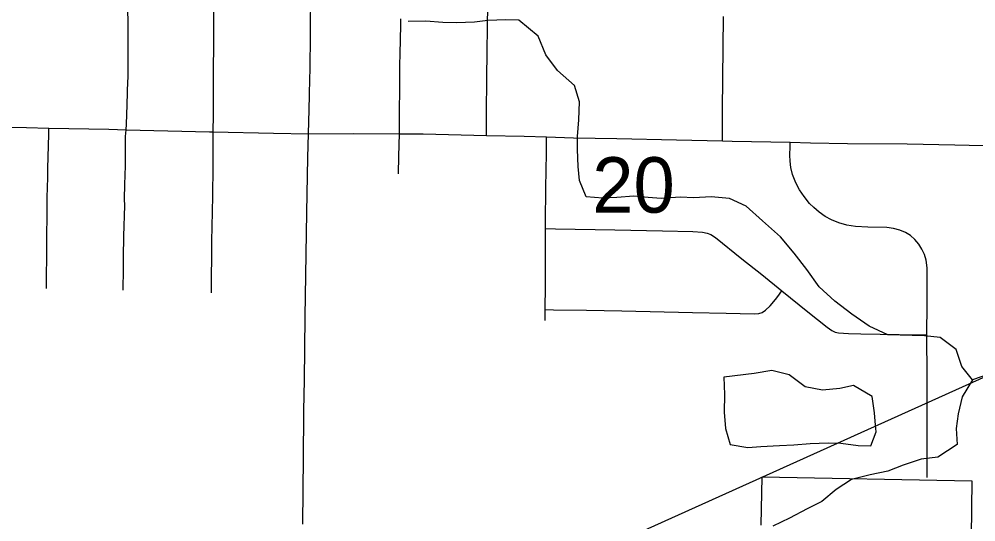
# Model space of a CAD drawing. Extents: x 0 to 34, y 0 to 22.
# Drawn here: x 6.731 to 7.454, y 16.761 to 17.141 of the extents above; entities that cross this region are included whole.
import ezdxf

# ---------------------------------------------------------------- set-up
doc = ezdxf.new("R2010")
doc.units = 0
for name, color, linetype in [('GM_X_City_Street', 7, 'Continuous'), ('GM_X_Corporation', 7, 'Continuous'), ('GM_X_County_Road', 7, 'Continuous'), ('GM_X_Minor_Lake', 7, 'Continuous'), ('GM_X_Minor_River', 7, 'Continuous'), ('GM_X_Section_Text', 7, 'Continuous'), ('GM_X_State_Route', 7, 'Continuous'), ('GM_X_US_Route', 7, 'Continuous'), ('SH_Data', 7, 'Continuous')]:
    doc.layers.add(name, color=color, linetype=linetype)

msp = doc.modelspace()

# ---------------------------------------------------------------- linework, layer by layer
at = {"layer": 'GM_X_City_Street'}
for points in [[(7.08428, 17.05289), (7.08428, 17.05616), (7.08427, 17.06975), (7.08456, 17.09583), (7.08478, 17.11632), (7.08501, 17.13421), (7.08585, 17.18692)], [(6.81005, 16.93612), (6.81018, 16.95227), (6.81013, 16.956), (6.81018, 16.95966), (6.81019, 16.96091), (6.81043, 16.97698), (6.81117, 16.99994), (6.81111, 17.00489), (6.81107, 17.00718), (6.81111, 17.01021), (6.81122, 17.01087), (6.81134, 17.01579), (6.81171, 17.02995), (6.81177, 17.05199), (6.81222, 17.05721), (6.81258, 17.06137), (6.81307, 17.07601), (6.81356, 17.09432), (6.81366, 17.09552), (6.81368, 17.10735), (6.81367, 17.13345), (6.81365, 17.13778), (6.81355, 17.1482)], [(6.87661, 16.93418), (6.87704, 16.97308), (6.87747, 16.99513), (6.87762, 17.0073), (6.87794, 17.02894), (6.87804, 17.05561), (6.87809, 17.06845), (6.87828, 17.10326), (6.87832, 17.12059), (6.87834, 17.13278), (6.87847, 17.14813)], [(7.01784, 17.02383), (7.0182, 17.03722), (7.01853, 17.05416), (7.01882, 17.10495), (7.01903, 17.11547), (7.01931, 17.12415), (7.0194, 17.1254), (7.01942, 17.12913), (7.01948, 17.1322), (7.01967, 17.14089)], [(6.75221, 16.93733), (6.75222, 16.94221), (6.75218, 16.94654), (6.75231, 16.96142), (6.75245, 16.98001), (6.75256, 16.98929), (6.75267, 16.99728), (6.75273, 17.00035), (6.7527, 17.00212), (6.75273, 17.0064), (6.75289, 17.01323), (6.75302, 17.02131), (6.75314, 17.028), (6.75378, 17.05392), (6.75389, 17.05848)], [(7.12851, 16.91329), (7.12857, 16.92148), (7.1287, 16.93927), (7.12877, 16.98263), (7.12878, 16.98721), (7.12911, 17.01336), (7.12953, 17.0395), (7.12952, 17.04838), (7.12952, 17.05175)], [(7.41688, 16.79467), (7.41689, 16.80583), (7.41682, 16.84054), (7.41688, 16.8536), (7.41693, 16.87097), (7.41676, 16.90239), (7.41674, 16.90576), (7.41691, 16.9225), (7.41702, 16.94363), (7.41688, 16.95301), (7.41612, 16.95867), (7.41487, 16.96297), (7.41299, 16.96705), (7.41054, 16.97083), (7.40762, 16.97425), (7.40428, 16.97724), (7.4005, 16.97969), (7.39637, 16.98146), (7.39143, 16.9827), (7.3864, 16.98332), (7.37208, 16.98363), (7.36287, 16.98418), (7.35623, 16.98524), (7.35035, 16.98684), (7.34467, 16.9891), (7.33986, 16.9917), (7.33539, 16.99485), (7.33127, 16.99851), (7.32822, 17.00148), (7.32398, 17.00668), (7.32056, 17.01176), (7.31778, 17.01719), (7.31536, 17.02346), (7.31402, 17.02874), (7.31345, 17.03357), (7.31337, 17.03791), (7.31352, 17.04458), (7.3136, 17.04768)], [(7.12877, 16.98263), (7.13632, 16.98249), (7.18103, 16.98166), (7.21706, 16.98089), (7.24003, 16.98044), (7.24735, 16.97992), (7.25083, 16.97916), (7.25354, 16.97803), (7.25707, 16.97573), (7.27693, 16.95986), (7.29201, 16.94785), (7.30728, 16.93559), (7.32689, 16.91984), (7.34137, 16.90812), (7.34508, 16.90556), (7.34748, 16.90447), (7.35004, 16.90385), (7.35758, 16.90336), (7.36695, 16.90327), (7.41041, 16.9025), (7.41676, 16.90239)], [(7.12857, 16.92148), (7.13489, 16.92137), (7.15971, 16.92092), (7.1864, 16.92046), (7.23977, 16.91916), (7.26523, 16.91876), (7.28629, 16.91818), (7.28982, 16.91847), (7.29248, 16.91938), (7.29491, 16.92097), (7.29842, 16.92429), (7.30238, 16.92896), (7.3042, 16.93144), (7.30728, 16.93559)]]:
    msp.add_lwpolyline(points, dxfattribs=at)
at = {"layer": 'GM_X_Corporation'}
msp.add_lwpolyline([(7.29168, 16.75869), (7.29237, 16.79534), (7.45064, 16.79234), (7.44905, 16.66612)], dxfattribs=at)
at = {"layer": 'GM_X_County_Road'}
for points in [[(7.26244, 17.0488), (7.26244, 17.0512), (7.26244, 17.05548), (7.26238, 17.06092), (7.2625, 17.07212), (7.26287, 17.11935), (7.26324, 17.14264)], [(6.69598, 17.05952), (6.73699, 17.05884), (6.75389, 17.05848)], [(6.75389, 17.05848), (6.79909, 17.05753), (6.81222, 17.05721)], [(6.81222, 17.05721), (6.87515, 17.05569), (6.87804, 17.05561)], [(6.87804, 17.05561), (6.92338, 17.05455), (6.94981, 17.05408)], [(6.94981, 17.05408), (6.98369, 17.05443), (7.01853, 17.05416)], [(7.01853, 17.05416), (7.03652, 17.05401), (7.08428, 17.05289)], [(7.08428, 17.05289), (7.11274, 17.05222), (7.12952, 17.05175)], [(7.12952, 17.05175), (7.15004, 17.05118), (7.18269, 17.05057), (7.2278, 17.04964), (7.26244, 17.0488)], [(7.26244, 17.0488), (7.26977, 17.04863), (7.3136, 17.04768)], [(7.3136, 17.04768), (7.32887, 17.04735), (7.35685, 17.04676), (7.40194, 17.04656), (7.43772, 17.04589), (7.47036, 17.04509), (7.54347, 17.04386), (7.58857, 17.04285), (7.62589, 17.0422), (7.64455, 17.04199), (7.67411, 17.04092), (7.7035, 17.03979), (7.71017, 17.03954)]]:
    msp.add_lwpolyline(points, dxfattribs=at)
at = {"layer": 'GM_X_Minor_Lake'}
for points in [[(7.37793, 16.83434), (7.37713, 16.84366), (7.37547, 16.85584), (7.36122, 16.86409), (7.35094, 16.86201), (7.33802, 16.86074), (7.3248, 16.86328), (7.31284, 16.87224), (7.29963, 16.87553), (7.28631, 16.87313), (7.26351, 16.87054)], [(7.26351, 16.87054), (7.26401, 16.85725), (7.26375, 16.84398), (7.26466, 16.83182), (7.26821, 16.81961), (7.28144, 16.81745), (7.29131, 16.81802), (7.30536, 16.81888), (7.31637, 16.81943), (7.32852, 16.82033), (7.34218, 16.82082), (7.35166, 16.82064), (7.36489, 16.81886), (7.37437, 16.81868), (7.37837, 16.82922), (7.37793, 16.83434)]]:
    msp.add_lwpolyline(points, dxfattribs=at)
at = {"layer": 'GM_X_Minor_River'}
for points in [[(7.45118, 16.86841), (7.44303, 16.87843), (7.43873, 16.89141), (7.42677, 16.90037), (7.41504, 16.90174), (7.38736, 16.90228), (7.37308, 16.90901), (7.35998, 16.91799), (7.34728, 16.92773), (7.33535, 16.93858), (7.32613, 16.95166), (7.31651, 16.96399), (7.30613, 16.97634), (7.29271, 16.98836), (7.28041, 16.99961), (7.26762, 17.00517), (7.254, 17.00657), (7.24071, 17.00569), (7.23048, 17.00627), (7.21605, 17.00541), (7.20621, 17.00599), (7.19561, 17.00695), (7.1827, 17.00606), (7.17207, 17.00551), (7.15957, 17.00652), (7.1545, 17.01876), (7.15357, 17.0294), (7.15306, 17.04231), (7.15287, 17.05218), (7.15387, 17.06468), (7.15452, 17.07833), (7.15058, 17.09055), (7.1379, 17.1018), (7.12903, 17.11374), (7.12324, 17.12789), (7.10868, 17.13994), (7.09883, 17.14013), (7.08516, 17.13964), (7.07528, 17.13832), (7.06162, 17.13782), (7.05138, 17.13802), (7.03851, 17.13903), (7.02523, 17.13891)], [(7.53129, 16.93249), (7.52579, 16.92273), (7.51611, 16.91229), (7.50343, 16.90381), (7.49188, 16.89493), (7.48524, 16.88481), (7.47563, 16.87817), (7.46416, 16.87308), (7.45118, 16.86841), (7.44334, 16.85566), (7.44044, 16.84281), (7.43871, 16.83184), (7.43962, 16.81968), (7.42502, 16.8101), (7.41248, 16.80845), (7.39874, 16.80416), (7.38727, 16.79945), (7.37395, 16.79668), (7.35985, 16.79316), (7.34833, 16.78579), (7.33753, 16.77652), (7.32643, 16.77104), (7.31302, 16.76409), (7.30039, 16.75789)]]:
    msp.add_lwpolyline(points, dxfattribs=at)
at = {"layer": 'GM_X_State_Route'}
for points in [[(6.95068, 17.08321), (6.95073, 17.08514), (6.95093, 17.09414), (6.95105, 17.10402), (6.95137, 17.12719), (6.9515, 17.13888), (6.95162, 17.15289), (6.95168, 17.16014), (6.9518, 17.17713), (6.95192, 17.18859), (6.95212, 17.20599), (6.95213, 17.21153)], [(6.94981, 17.05408), (6.95041, 17.07257), (6.95068, 17.08321)], [(6.94681, 16.86823), (6.94748, 16.91609), (6.94851, 16.99462), (6.94932, 17.03626), (6.94981, 17.05408)], [(6.94583, 16.78786), (6.94622, 16.80679), (6.94648, 16.8453), (6.94681, 16.86823)], [(6.9456, 16.75962), (6.94562, 16.76062), (6.94575, 16.78388), (6.94583, 16.78786)]]:
    msp.add_lwpolyline(points, dxfattribs=at)
at = {"layer": 'GM_X_US_Route'}
for points in [[(6.95068, 17.08321), (6.95073, 17.08514), (6.95093, 17.09414), (6.95105, 17.10402), (6.95137, 17.12719), (6.9515, 17.13888), (6.95162, 17.15289), (6.95168, 17.16014), (6.9518, 17.17713), (6.95192, 17.18859), (6.95212, 17.20599), (6.95213, 17.21153)], [(6.94981, 17.05408), (6.95041, 17.07257), (6.95068, 17.08321)], [(6.94681, 16.86823), (6.94748, 16.91609), (6.94851, 16.99462), (6.94932, 17.03626), (6.94981, 17.05408)], [(6.94583, 16.78786), (6.94622, 16.80679), (6.94648, 16.8453), (6.94681, 16.86823)], [(6.9456, 16.75962), (6.94562, 16.76062), (6.94575, 16.78388), (6.94583, 16.78786)]]:
    msp.add_lwpolyline(points, dxfattribs=at)
at = {"layer": 'SH_Data'}
msp.add_lwpolyline([(4.57396, 15.57027), (9.28135, 17.20113), (9.28135, 17.69113)], close=True, dxfattribs=at)

# ---------------------------------------------------------------- texts
at = {"layer": 'GM_X_Section_Text'}
msp.add_text('20', height=0.041856, rotation=0.00001, dxfattribs=at).set_placement((7.16414, 16.99458))

doc.saveas('drawing.dxf')
